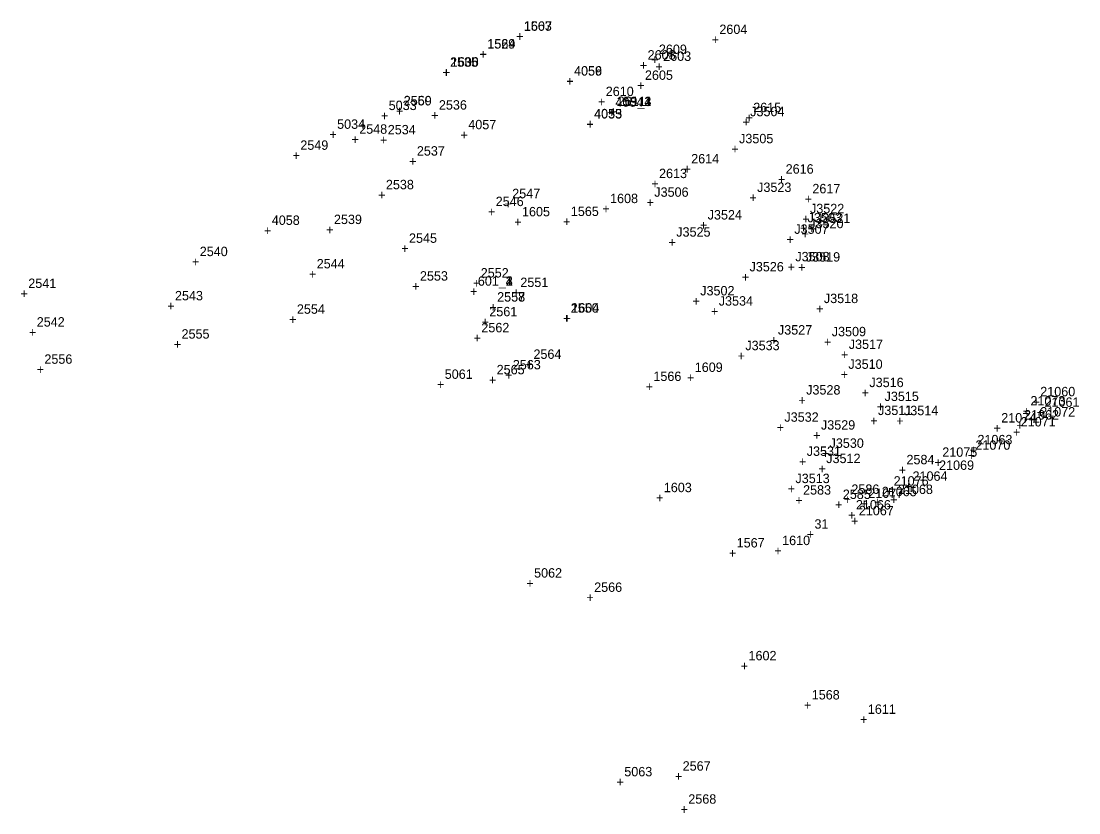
# Model space of a CAD drawing. Extents: x 1036751 to 1042192, y 772604 to 785439.
# Drawn here: x 1038827.9 to 1039109.1, y 777609 to 777819.5 of the extents above; entities that cross this region are included whole.
import ezdxf

# ---------------------------------------------------------------- set-up
doc = ezdxf.new("R2010")
doc.units = 0
for name, color, linetype in [('S_Buildings', 7, 'Continuous'), ('S_Buildings_Attachments', 7, 'Continuous'), ('S_Buildings_SillElevation', 7, 'Continuous'), ('S_Control_Geodetic_ControlPoint', 7, 'Continuous'), ('S_Control_Temp_Traverse', 7, 'Continuous'), ('S_Drainage_Culvert_Top', 7, 'Continuous'), ('S_Drainage_Invert', 7, 'Continuous'), ('S_Fencing_Electric', 7, 'Continuous'), ('S_Ground_Elevation', 7, 'Continuous'), ('S_Ground_LevelString', 7, 'Continuous'), ('S_Property_IronPipeFound', 7, 'Continuous'), ('S_Property_StoneWall', 7, 'Continuous'), ('S_Roadway_Centerline', 7, 'Continuous'), ('S_Roadway_Drive_Gravel', 7, 'Continuous'), ('S_Roadway_Edge_Pavement', 7, 'Continuous'), ('S_Traffic_Sign_DoublePost', 7, 'Continuous'), ('S_Traffic_Sign_SinglePost', 7, 'Continuous'), ('S_Trees_Conifer_Pay', 7, 'Continuous'), ('S_Trees_Decid_Pay', 7, 'Continuous'), ('S_Utilities_Hydrant', 7, 'Continuous'), ('S_Utilities_Pole_Power', 7, 'Continuous'), ('S_Utilities_UG_Water_Line', 7, 'Continuous')]:
    doc.layers.add(name, color=color, linetype=linetype)

msp = doc.modelspace()

# ---------------------------------------------------------------- texts
at = {"layer": 'S_Buildings'}
for s, p in [('2604', (1039013.52, 777816.12)), ('+', (1039011.46, 777813.37)), ('2603', (1038998.58, 777808.97)), ('+', (1038996.52, 777806.22)), ('2615', (1039022.52, 777795.34)), ('+', (1039020.46, 777792.59)), ('2616', (1039031.15, 777778.98)), ('+', (1039029.09, 777776.23))]:
    msp.add_text(s, height=2.5, dxfattribs=at).set_placement(p)
at = {"layer": 'S_Buildings_Attachments'}
for s, p in [('2609', (1038997.44, 777810.81)), ('2608', (1038994.44, 777809.32)), ('+', (1038995.38, 777808.07)), ('+', (1038992.38, 777806.57))]:
    msp.add_text(s, height=2.5, dxfattribs=at).set_placement(p)
at = {"layer": 'S_Buildings_SillElevation'}
for s, p in [('2617', (1039038.25, 777773.75)), ('+', (1039036.19, 777771))]:
    msp.add_text(s, height=2.5, dxfattribs=at).set_placement(p)
at = {"layer": 'S_Control_Geodetic_ControlPoint'}
for s, p in [('31', (1039038.8, 777684.55)), ('31', (1039038.8, 777684.55)), ('31', (1039038.8, 777684.55)), ('31', (1039038.8, 777684.55)), ('31', (1039038.8, 777684.55)), ('31', (1039038.8, 777684.55)), ('31', (1039038.8, 777684.55)), ('31', (1039038.8, 777684.55)), ('31', (1039038.8, 777684.55)), ('+', (1039036.74, 777681.8)), ('+', (1039036.74, 777681.8)), ('+', (1039036.74, 777681.8)), ('+', (1039036.74, 777681.8)), ('+', (1039036.74, 777681.8)), ('+', (1039036.74, 777681.8)), ('+', (1039036.74, 777681.8)), ('+', (1039036.74, 777681.8)), ('+', (1039036.74, 777681.8))]:
    msp.add_text(s, height=2.5, dxfattribs=at).set_placement(p)
at = {"layer": 'S_Control_Temp_Traverse'}
for s, p in [('159', (1038986.14, 777796.95)), ('159_1', (1038986.14, 777796.95)), ('159_3', (1038986.14, 777796.95)), ('159_2', (1038986.14, 777796.95)), ('159_4', (1038986.14, 777796.95)), ('+', (1038984.08, 777794.2)), ('+', (1038984.08, 777794.2)), ('+', (1038984.08, 777794.2)), ('+', (1038984.08, 777794.2)), ('+', (1038984.08, 777794.2)), ('601', (1038949.3, 777749.17)), ('601_4', (1038949.3, 777749.17)), ('601_2', (1038949.3, 777749.17)), ('601_3', (1038949.3, 777749.17)), ('601_1', (1038949.3, 777749.17)), ('+', (1038947.24, 777746.42)), ('+', (1038947.24, 777746.42)), ('+', (1038947.24, 777746.42)), ('+', (1038947.24, 777746.42)), ('+', (1038947.24, 777746.42))]:
    msp.add_text(s, height=2.5, dxfattribs=at).set_placement(p)
at = {"layer": 'S_Drainage_Culvert_Top'}
for s, p in [('2559', (1038929.61, 777797.12)), ('+', (1038927.55, 777794.37)), ('2558', (1038954.44, 777744.94)), ('+', (1038952.38, 777742.19))]:
    msp.add_text(s, height=2.5, dxfattribs=at).set_placement(p)
at = {"layer": 'S_Drainage_Invert'}
for s, p in [('2560', (1038929.57, 777797.17)), ('+', (1038927.51, 777794.42)), ('2557', (1038954.43, 777744.96)), ('+', (1038952.37, 777742.21))]:
    msp.add_text(s, height=2.5, dxfattribs=at).set_placement(p)
at = {"layer": 'S_Fencing_Electric'}
for s, p in [('2584', (1039063.27, 777701.68)), ('+', (1039061.21, 777698.93)), ('2585', (1039046.34, 777692.45)), ('+', (1039044.28, 777689.7))]:
    msp.add_text(s, height=2.5, dxfattribs=at).set_placement(p)
at = {"layer": 'S_Ground_Elevation'}
for s, p in [('5033', (1038925.59, 777795.89)), ('5034', (1038911.89, 777790.9)), ('+', (1038923.53, 777793.14)), ('+', (1038909.83, 777788.15)), ('J3523', (1039023.56, 777774.11)), ('+', (1039021.5, 777771.36)), ('J3522', (1039037.62, 777768.45)), ('J3524', (1039010.41, 777766.78)), ('J3521', (1039039.22, 777765.87)), ('+', (1039008.35, 777764.03)), ('+', (1039035.56, 777765.7)), ('+', (1039037.16, 777763.12)), ('J3520', (1039037.42, 777764.47)), ('J3525', (1039002.06, 777762.22)), ('+', (1039035.36, 777761.72)), ('+', (1039000, 777759.47)), ('J3519', (1039036.52, 777755.58)), ('J3526', (1039021.54, 777752.98)), ('+', (1039034.46, 777752.83)), ('+', (1039019.48, 777750.23)), ('J3534', (1039013.36, 777743.88)), ('J3518', (1039041.31, 777744.55)), ('+', (1039011.3, 777741.13)), ('+', (1039039.25, 777741.8)), ('J3527', (1039029.09, 777736.18)), ('J3533', (1039020.43, 777732.02)), ('+', (1039027.03, 777733.43)), ('J3517', (1039047.93, 777732.35)), ('+', (1039018.37, 777729.27)), ('+', (1039045.87, 777729.6)), ('5061', (1038940.5, 777724.4)), ('+', (1038938.44, 777721.65)), ('J3516', (1039053.41, 777722.2)), ('J3528', (1039036.6, 777720.23)), ('+', (1039051.34, 777719.45)), ('J3515', (1039057.45, 777718.5)), ('+', (1039034.54, 777717.48)), ('+', (1039055.39, 777715.75)), ('J3514', (1039062.61, 777714.73)), ('21073', (1039096.22, 777717.32)), ('J3532', (1039030.81, 777712.99)), ('21074', (1039088.46, 777712.79)), ('+', (1039094.16, 777714.57)), ('21072', (1039098.83, 777714.38)), ('+', (1039028.75, 777710.24)), ('J3529', (1039040.53, 777710.89)), ('+', (1039060.55, 777711.98)), ('+', (1039086.4, 777710.04)), ('21071', (1039093.64, 777711.73)), ('+', (1039096.77, 777711.63)), ('+', (1039038.47, 777708.14)), ('+', (1039091.58, 777708.98)), ('J3531', (1039036.75, 777703.91)), ('J3530', (1039042.82, 777706.05)), ('21075', (1039072.79, 777703.66)), ('21070', (1039081.6, 777705.54)), ('+', (1039034.69, 777701.16)), ('+', (1039040.76, 777703.3)), ('+', (1039079.54, 777702.79)), ('+', (1039070.73, 777700.91)), ('21069', (1039071.94, 777700.19)), ('21076', (1039059.86, 777696)), ('+', (1039069.88, 777697.44)), ('21077', (1039053.12, 777692.72)), ('+', (1039057.8, 777693.25)), ('21068', (1039061, 777693.77)), ('+', (1039051.06, 777689.97)), ('+', (1039058.94, 777691.02)), ('21067', (1039050.6, 777688.11)), ('+', (1039048.54, 777685.36)), ('5062', (1038964.26, 777671.54)), ('+', (1038962.2, 777668.79)), ('5063', (1038988.24, 777618.68)), ('+', (1038986.17, 777615.93))]:
    msp.add_text(s, height=2.5, dxfattribs=at).set_placement(p)
at = {"layer": 'S_Ground_LevelString'}
for s, p in [('1606', (1038942.1, 777807.45)), ('+', (1038940.04, 777804.7)), ('1605', (1038961.04, 777767.62)), ('+', (1038958.98, 777764.87))]:
    msp.add_text(s, height=2.5, dxfattribs=at).set_placement(p)
at = {"layer": 'S_Property_IronPipeFound'}
for s, p in [('2605', (1038993.73, 777803.93)), ('+', (1038991.67, 777801.18)), ('2562', (1038950.24, 777736.78)), ('+', (1038948.17, 777734.03)), ('2586', (1039048.62, 777693.81)), ('+', (1039046.56, 777691.06))]:
    msp.add_text(s, height=2.5, dxfattribs=at).set_placement(p)
at = {"layer": 'S_Property_StoneWall'}
for s, p in [('21060', (1039098.84, 777719.77)), ('+', (1039096.78, 777717.02)), ('21061', (1039099.97, 777716.96)), ('21062', (1039094.52, 777713.58)), ('+', (1039097.91, 777714.21)), ('+', (1039092.46, 777710.83)), ('21063', (1039082.14, 777706.99)), ('+', (1039080.08, 777704.24)), ('21064', (1039064.88, 777697.28)), ('21065', (1039056.7, 777693.18)), ('+', (1039062.82, 777694.53)), ('21066', (1039049.82, 777689.66)), ('+', (1039054.63, 777690.43)), ('+', (1039047.76, 777686.91))]:
    msp.add_text(s, height=2.5, dxfattribs=at).set_placement(p)
at = {"layer": 'S_Roadway_Centerline'}
for s, p in [('1529', (1038951.8, 777812.25)), ('1564', (1038951.84, 777812.27)), ('+', (1038949.74, 777809.5)), ('+', (1038949.78, 777809.52)), ('2547', (1038958.44, 777772.45)), ('2546', (1038954.05, 777770.35)), ('+', (1038956.38, 777769.7)), ('+', (1038951.99, 777767.6)), ('1565', (1038974.03, 777767.71)), ('+', (1038971.97, 777764.96)), ('2545', (1038930.99, 777760.58)), ('+', (1038928.93, 777757.83)), ('2544', (1038906.46, 777753.78)), ('+', (1038904.4, 777751.03)), ('2543', (1038868.77, 777745.28)), ('+', (1038866.71, 777742.53)), ('2542', (1038832.02, 777738.3)), ('+', (1038829.96, 777735.55)), ('1566', (1038995.98, 777723.83)), ('+', (1038993.92, 777721.08)), ('1567', (1039018.12, 777679.55)), ('+', (1039016.06, 777676.8)), ('1568', (1039038.08, 777639.12)), ('+', (1039036.02, 777636.37))]:
    msp.add_text(s, height=2.5, dxfattribs=at).set_placement(p)
at = {"layer": 'S_Roadway_Drive_Gravel'}
for s, p in [('J3504', (1039021.72, 777794.25)), ('+', (1039019.66, 777791.5)), ('J3505', (1039018.76, 777787.06)), ('+', (1039016.7, 777784.31)), ('J3506', (1038996.22, 777772.83)), ('+', (1038994.16, 777770.08)), ('J3503', (1039036.99, 777766.04)), ('J3507', (1039033.45, 777762.97)), ('+', (1039034.93, 777763.29)), ('+', (1039031.38, 777760.22)), ('J3508', (1039033.72, 777755.66)), ('+', (1039031.66, 777752.91)), ('J3502', (1039008.43, 777746.59)), ('+', (1039006.37, 777743.84)), ('J3509', (1039043.41, 777735.73)), ('+', (1039041.35, 777732.98)), ('J3510', (1039047.82, 777727.06)), ('+', (1039045.76, 777724.31)), ('J3511', (1039055.7, 777714.77)), ('+', (1039053.64, 777712.02)), ('J3512', (1039041.94, 777701.99)), ('+', (1039039.88, 777699.24)), ('J3513', (1039033.75, 777696.67)), ('+', (1039031.69, 777693.92))]:
    msp.add_text(s, height=2.5, dxfattribs=at).set_placement(p)
at = {"layer": 'S_Roadway_Edge_Pavement'}
for s, p in [('1563', (1038961.53, 777817)), ('1607', (1038961.56, 777816.96)), ('+', (1038959.47, 777814.25)), ('+', (1038959.5, 777814.21)), ('2535', (1038941.91, 777807.42)), ('1530', (1038942.08, 777807.42)), ('+', (1038939.85, 777804.67)), ('+', (1038940.02, 777804.67)), ('2536', (1038938.95, 777796.01)), ('+', (1038936.88, 777793.26)), ('2537', (1038933.09, 777783.78)), ('+', (1038931.03, 777781.03)), ('2538', (1038924.86, 777774.83)), ('+', (1038922.8, 777772.08)), ('1608', (1038984.46, 777771.14)), ('2539', (1038911.04, 777765.57)), ('+', (1038982.4, 777768.39)), ('+', (1038908.98, 777762.82)), ('2540', (1038875.36, 777757.04)), ('+', (1038873.3, 777754.29)), ('2552', (1038950.07, 777751.35)), ('2541', (1038829.77, 777748.57)), ('2553', (1038933.91, 777750.53)), ('2551', (1038960.6, 777748.82)), ('+', (1038931.85, 777747.78)), ('+', (1038948.01, 777748.6)), ('+', (1038827.71, 777745.82)), ('+', (1038958.54, 777746.07)), ('2554', (1038901.19, 777741.71)), ('2550', (1038973.99, 777742)), ('1604', (1038974.16, 777742.04)), ('+', (1038899.13, 777738.96)), ('+', (1038971.92, 777739.25)), ('+', (1038972.1, 777739.29)), ('2555', (1038870.52, 777735.1)), ('+', (1038868.46, 777732.35)), ('2556', (1038834.05, 777728.41)), ('1609', (1039006.97, 777726.24)), ('+', (1038831.99, 777725.66)), ('+', (1039004.91, 777723.49)), ('1603', (1038998.75, 777694.26)), ('+', (1038996.69, 777691.51)), ('1610', (1039030.21, 777680.18)), ('+', (1039028.14, 777677.43)), ('1602', (1039021.27, 777649.54)), ('+', (1039019.21, 777646.79)), ('1611', (1039053, 777635.3)), ('+', (1039050.93, 777632.55))]:
    msp.add_text(s, height=2.5, dxfattribs=at).set_placement(p)
at = {"layer": 'S_Traffic_Sign_DoublePost'}
for s, p in [('2564', (1038964.09, 777729.72)), ('2563', (1038958.6, 777726.92)), ('+', (1038962.03, 777726.97)), ('+', (1038956.54, 777724.17))]:
    msp.add_text(s, height=2.5, dxfattribs=at).set_placement(p)
at = {"layer": 'S_Traffic_Sign_SinglePost'}
for s, p in [('2610', (1038983.31, 777799.61)), ('+', (1038981.25, 777796.86)), ('2548', (1038917.76, 777789.59)), ('2534', (1038925.35, 777789.43)), ('+', (1038915.7, 777786.84)), ('+', (1038923.29, 777786.68)), ('2613', (1038997.48, 777777.79)), ('+', (1038995.42, 777775.04)), ('2561', (1038952.35, 777741.04)), ('+', (1038950.29, 777738.29))]:
    msp.add_text(s, height=2.5, dxfattribs=at).set_placement(p)
at = {"layer": 'S_Trees_Conifer_Pay'}
for s, p in [('2549', (1038902.1, 777785.32)), ('+', (1038900.04, 777782.57)), ('2565', (1038954.3, 777725.61)), ('+', (1038952.24, 777722.86)), ('2568', (1039005.26, 777611.4)), ('+', (1039003.2, 777608.65))]:
    msp.add_text(s, height=2.5, dxfattribs=at).set_placement(p)
at = {"layer": 'S_Trees_Decid_Pay'}
for s, p in [('2614', (1039006.03, 777781.71)), ('+', (1039003.97, 777778.96)), ('2566', (1038980.23, 777667.74)), ('+', (1038978.17, 777664.99)), ('2567', (1039003.76, 777620.19)), ('+', (1039001.7, 777617.44))]:
    msp.add_text(s, height=2.5, dxfattribs=at).set_placement(p)
at = {"layer": 'S_Utilities_Hydrant'}
for s, p in [('2611', (1038986.47, 777796.98)), ('+', (1038984.41, 777794.23))]:
    msp.add_text(s, height=2.5, dxfattribs=at).set_placement(p)
at = {"layer": 'S_Utilities_Pole_Power'}
for s, p in [('2583', (1039035.78, 777693.61)), ('+', (1039033.72, 777690.86))]:
    msp.add_text(s, height=2.5, dxfattribs=at).set_placement(p)
at = {"layer": 'S_Utilities_UG_Water_Line'}
for s, p in [('4059', (1038974.87, 777805.05)), ('4056', (1038974.89, 777805.09)), ('+', (1038972.83, 777802.34)), ('+', (1038972.81, 777802.3)), ('4054', (1038985.88, 777796.77)), ('4055', (1038980.22, 777793.71)), ('4053', (1038980.22, 777793.63)), ('+', (1038983.82, 777794.02)), ('4057', (1038946.76, 777790.79)), ('+', (1038978.16, 777790.96)), ('+', (1038978.16, 777790.88)), ('+', (1038944.7, 777788.04)), ('4058', (1038894.51, 777765.35)), ('+', (1038892.45, 777762.6))]:
    msp.add_text(s, height=2.5, dxfattribs=at).set_placement(p)

doc.saveas('drawing.dxf')
